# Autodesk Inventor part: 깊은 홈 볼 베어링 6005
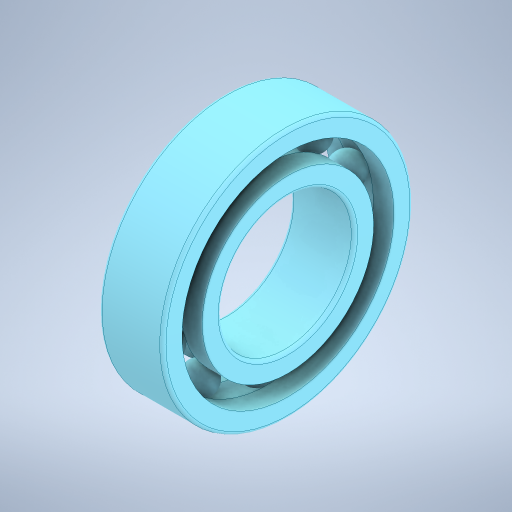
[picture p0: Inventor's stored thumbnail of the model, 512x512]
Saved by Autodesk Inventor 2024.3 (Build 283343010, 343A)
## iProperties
Created: 2025-11
Part Number: 깊은 홈 볼 베어링 6005
Material: 강철, 연강
Description: 깊은 그루브 볼 베어링
Document SubType Name: Modeling
Designer: PC2-15
Density: 7.85 g/cm^3
Appearance: 기본값
Author: jhkim
Sending System: Autodesk Inventor 2026
Preprocessor: ST-DEVELOPER v20.1
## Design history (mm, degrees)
node "깊은 홈 볼 베어링 60051"
node "솔리드1"
node "솔리드2"
node "솔리드3"
node "솔리드4"
node "솔리드5"
node "솔리드6"
node "솔리드7"
node "솔리드8"
node "솔리드9"
node "솔리드10"
node "솔리드11"
node "솔리드12"
body "Solid1"
node "Solid1:1"
node "Solid1:2"
node "Solid1:3"
node "Solid1:4"
node "Solid1:5"
node "Solid1:6"
node "Solid1:7"
node "Solid1:8"
node "Solid1:9"
node "Solid1:10"
node "Solid1:11"
